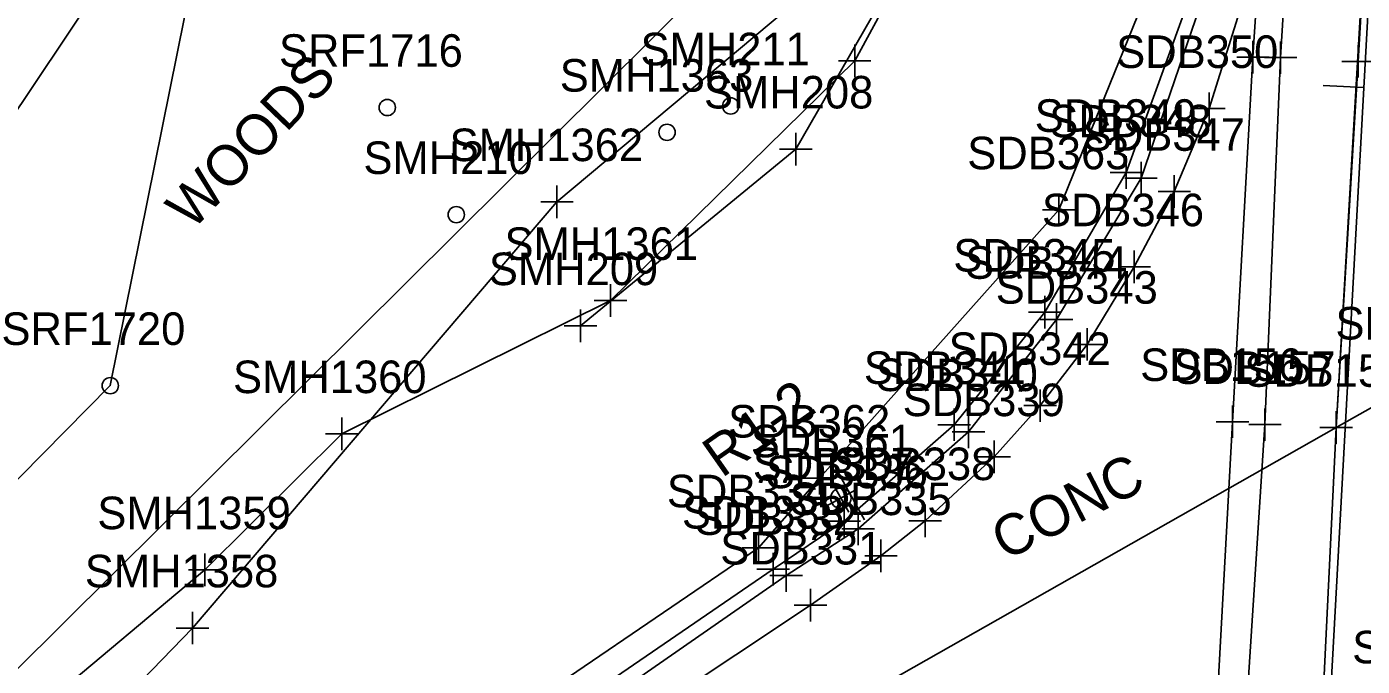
# Model space of a CAD drawing. Extents: x 941041 to 969446, y 397014 to 416764.
# Drawn here: x 951726.5 to 951890.6, y 403555.2 to 403633.8 of the extents above; entities that cross this region are included whole.
import ezdxf

# ---------------------------------------------------------------- set-up
doc = ezdxf.new("R2010")
doc.units = 0
for name, color, linetype in [('SURVEY - CENTERLINE - Preliminary', 7, 'Continuous'), ('SURVEY - CENTERLINE - Preliminary Curve Text', 7, 'Continuous'), ('SURVEY - DRAINAGE - Area Shapes', 7, 'Continuous'), ('SURVEY - DTM - Breaklines', 7, 'Continuous'), ('SURVEY - DTM - Breaklines - Points - Locators', 7, 'Continuous'), ('SURVEY - DTM - Breaklines - Points - Numbers', 7, 'Continuous'), ('SURVEY - DTM - Spot Points - Locators', 7, 'Continuous'), ('SURVEY - DTM - Spot Points - Point Numbers', 7, 'Continuous'), ('SURVEY - DTM GRAPHICS - Boundary Line', 7, 'Continuous'), ('SURVEY - NON-TRANSPORTATION - Features', 7, 'Continuous'), ('SURVEY - ROADSIDE BARRIERS - Points - Locators', 7, 'Continuous'), ('SURVEY - ROADSIDE BARRIERS - Points - Numbers', 7, 'Continuous'), ('SURVEY - ROADSIDE BARRIERS with Text', 7, 'Continuous'), ('SURVEY - TRAFFIC CONTROL - Signs - Points - Locators', 7, 'Continuous'), ('SURVEY - TRAFFIC CONTROL - Signs - Points - Numbers', 7, 'Continuous'), ('SURVEY - TRAFFIC CONTROL - Signs and Devices with Text', 7, 'Continuous'), ('SURVEY - TRANSPORTATION - Features Text', 7, 'Continuous'), ('SURVEY - TRANSPORTATION - Roads', 7, 'Continuous'), ('SURVEY - TRANSPORTATION - Roads - Points - Locators', 7, 'Continuous'), ('SURVEY - TRANSPORTATION - Roads - Points - Numbers', 7, 'Continuous'), ('SURVEY - VEGETATION - Features - Points - Locators', 7, 'Continuous'), ('SURVEY - VEGETATION - Features - Points - Numbers', 7, 'Continuous'), ('SURVEY - VEGETATION - Features with Text', 7, 'Continuous')]:
    doc.layers.add(name, color=color, linetype=linetype)

msp = doc.modelspace()

# ---------------------------------------------------------------- linework, layer by layer
at = {"layer": 'SURVEY - CENTERLINE - Preliminary'}
msp.add_line((951818.98, 402312.97), (951929.94, 404341.52), dxfattribs=at)
at = {"layer": 'SURVEY - CENTERLINE - Preliminary Curve Text'}
msp.add_line((951890.82, 403626.35), (951885.83, 403626.62), dxfattribs=at)
at = {"layer": 'SURVEY - DRAINAGE - Area Shapes'}
for points in [[(951394.91, 403299.54), (951490.14, 404032.2), (951534.57, 404027.31), (951536.74, 404050.34), (951913.12, 404038.39), (951897.46, 403756.49), (951887.41, 403584.59), (951722.84, 403491.25), (951657.46, 403432.19), (951570.1, 403333.86)], [(951145.6, 402792.15), (951562.19, 403084.02), (952475.83, 403724.71), (952754.77, 403922.8), (952578.99, 403846.21), (952455.44, 403792), (952334.19, 403750.29), (951972.51, 403632.53), (951887.41, 403584.59)]]:
    msp.add_lwpolyline(points, dxfattribs=at)
at = {"layer": 'SURVEY - DTM - Breaklines'}
for points in [[(951899.88, 403797.03), (951897.46, 403756.49), (951895.1, 403715.33), (951892.65, 403672.69), (951890.1, 403629.58), (951887.41, 403584.59), (951885.29, 403540.64), (951882.61, 403490.83), (951880.06, 403438.72), (951877.65, 403396.76)], [(951641.86, 403426.67), (951653.35, 403439.13), (951682.38, 403468.13), (951717.4, 403498.12), (951748.42, 403523.14), (951781.37, 403545.95), (951816.39, 403569.78), (951823.92, 403578.35), (951853.31, 403611.32), (951868.71, 403649.22), (951877.42, 403681.51), (951874.12, 403698.41), (951861.93, 403712.77), (951840.77, 403717.4), (951813.39, 403710.78), (951800.96, 403703.16), (951769.1, 403675.11), (951738.55, 403643.48)], [(951746.79, 403639.72), (951784.08, 403673.17), (951825.91, 403698.88), (951848.16, 403703.12), (951841.56, 403654.59), (951820.99, 403618.79), (951794.53, 403597.08)], [(951504.25, 403257.1), (951548.43, 403354.82), (951588.18, 403418.84), (951641.86, 403470.19), (951672.49, 403500.14), (951709.08, 403534.17), (951748.34, 403567.09), (951765.19, 403583.81), (951798.22, 403600.18), (951828.23, 403629.65), (951839.94, 403651.21), (951840.47, 403661.39)]]:
    msp.add_lwpolyline(points, dxfattribs=at)
at = {"layer": 'SURVEY - DTM - Breaklines - Points - Locators'}
for p, q in [((951828.23, 403631.65), (951828.23, 403627.65)), ((951890.1, 403631.58), (951890.1, 403627.58)), ((951830.23, 403629.65), (951826.23, 403629.65)), ((951892.1, 403629.58), (951888.1, 403629.58)), ((951820.99, 403620.79), (951820.99, 403616.79)), ((951822.99, 403618.79), (951818.99, 403618.79)), ((951853.31, 403613.32), (951853.31, 403609.32)), ((951855.31, 403611.32), (951851.31, 403611.32)), ((951798.22, 403602.18), (951798.22, 403598.18)), ((951794.53, 403599.08), (951794.53, 403595.08)), ((951800.22, 403600.18), (951796.22, 403600.18)), ((951796.53, 403597.08), (951792.53, 403597.08)), ((951765.19, 403585.81), (951765.19, 403581.81)), ((951887.41, 403586.59), (951887.41, 403582.59)), ((951889.41, 403584.59), (951885.41, 403584.59)), ((951767.19, 403583.81), (951763.19, 403583.81)), ((951823.92, 403580.35), (951823.92, 403576.35)), ((951825.92, 403578.35), (951821.92, 403578.35)), ((951816.39, 403571.78), (951816.39, 403567.78)), ((951818.39, 403569.78), (951814.39, 403569.78)), ((951748.34, 403569.09), (951748.34, 403565.09)), ((951750.34, 403567.09), (951746.34, 403567.09))]:
    msp.add_line(p, q, dxfattribs=at)
at = {"layer": 'SURVEY - DTM - Spot Points - Locators'}
for centre in [(951770.78, 403623.91), (951812.99, 403624.1), (951805.17, 403620.86), (951779.26, 403610.74), (951736.73, 403589.73)]:
    msp.add_circle(centre, 1, dxfattribs=at)
at = {"layer": 'SURVEY - DTM GRAPHICS - Boundary Line'}
msp.add_lwpolyline([(951575.07, 404018.69), (951594.81, 403959.15), (951592.33, 403907.04), (951593.34, 403830.61), (951643.02, 403826.18), (951710.4, 403762.77), (951727.47, 403714.2), (951716.98, 403687.98), (951730.3, 403662.6), (951739.47, 403650.39), (951738.55, 403643.5), (951746.79, 403639.72), (951736.73, 403589.73), (951706.43, 403559.07), (951672.49, 403500.14), (951641.86, 403470.19), (951622.56, 403452.94), (951588.18, 403418.84), (951548.43, 403354.82), (951490.75, 403254.61), (951405.32, 403106.55), (950864.72, 402727.75)], dxfattribs=at)
at = {"layer": 'SURVEY - NON-TRANSPORTATION - Features'}
msp.add_lwpolyline([(950864.72, 402727.75), (951405.32, 403106.55), (951490.75, 403254.61), (951622.56, 403452.94), (951851.46, 403680.18), (951878.49, 403682.56)], dxfattribs=at)
at = {"layer": 'SURVEY - ROADSIDE BARRIERS - Points - Locators'}
for p, q in [((951861.62, 403617.92), (951861.62, 403613.92)), ((951863.62, 403615.92), (951859.62, 403615.92)), ((951851.6, 403600.75), (951851.6, 403596.75)), ((951853.6, 403598.75), (951849.6, 403598.75)), ((951840.45, 403586.93), (951840.45, 403582.93)), ((951842.45, 403584.93), (951838.45, 403584.93)), ((951826.95, 403575.08), (951826.95, 403571.08)), ((951828.95, 403573.08), (951824.95, 403573.08)), ((951818.22, 403569.17), (951818.22, 403565.17)), ((951820.22, 403567.17), (951816.22, 403567.17))]:
    msp.add_line(p, q, dxfattribs=at)
at = {"layer": 'SURVEY - ROADSIDE BARRIERS with Text'}
msp.add_lwpolyline([(951653.32, 403436.82), (951685.14, 403466.86), (951718.82, 403496.01), (951750.67, 403520.29), (951783.21, 403543.21), (951818.22, 403567.17), (951826.95, 403573.08), (951840.45, 403584.93), (951851.6, 403598.75), (951861.62, 403615.92), (951871.85, 403644.2), (951877.9, 403666.33), (951881.14, 403687.36), (951881.18, 403694.17), (951880.19, 403699.57), (951876.73, 403707.33), (951867.26, 403722.8)], dxfattribs=at)
at = {"layer": 'SURVEY - TRAFFIC CONTROL - Signs - Points - Locators'}
for p, q in [((951827.51, 403574.17), (951825.56, 403577.67)), ((951824.79, 403574.94), (951828.29, 403576.89))]:
    msp.add_line(p, q, dxfattribs=at)
at = {"layer": 'SURVEY - TRAFFIC CONTROL - Signs and Devices with Text'}
msp.add_line((951825.78, 403579.79), (951829.44, 403573.24), dxfattribs=at)
msp.add_circle((951826.53, 403575.89), 1.25, dxfattribs=at)
at = {"layer": 'SURVEY - TRANSPORTATION - Roads'}
for points in [[(951889.67, 403798.15), (951887.47, 403762.39), (951886.39, 403756.98), (951884.11, 403714.99), (951881.77, 403672.24), (951879.03, 403658.08), (951877.19, 403630.1), (951874.68, 403585.3), (951872.31, 403541.8), (951869.92, 403493.49), (951868.53, 403439.12), (951866.21, 403388.53), (951867.61, 403389.53)], [(951889.67, 403798.15), (951887.47, 403762.39), (951886.39, 403756.98), (951884.11, 403714.99), (951881.77, 403672.24), (951879.03, 403658.08), (951877.19, 403630.1), (951874.68, 403585.3), (951872.31, 403541.8), (951869.92, 403493.49), (951868.53, 403439.12), (951866.69, 403400.46)], [(951890.4, 403798.17), (951888, 403756.83), (951885.32, 403715.18), (951883.22, 403673.16), (951880.59, 403630.04), (951878.66, 403584.94), (951875.81, 403541.16), (951872.77, 403491.83), (951870.34, 403439.11), (951867.61, 403389.53)], [(951411.81, 403052.83), (951433.79, 403086.48), (951455, 403125.01), (951474.14, 403165.06), (951492.87, 403205.4), (951511.64, 403243.43), (951531.76, 403279.81), (951554.15, 403314.52), (951581.05, 403351.18), (951610.77, 403387.99), (951640.83, 403422.39), (951654.46, 403436.04), (951686.11, 403466.26), (951719.67, 403495.18), (951751.88, 403518.68), (951783.82, 403541.39), (951819.82, 403566.39), (951828.66, 403572.13), (951842.23, 403584.06), (951853.04, 403597.86), (951863.43, 403615.24), (951873.23, 403643.85), (951879.03, 403658.08)], [(951536.17, 403276.66), (951558.52, 403311.6), (951584.36, 403348.13), (951613.6, 403384.66), (951644.16, 403418.6), (951657.46, 403432.19), (951689.75, 403463.06), (951722.84, 403491.25), (951754.66, 403515.84), (951785.97, 403538.25), (951822.79, 403562.75), (951831.46, 403568.82), (951836.89, 403573.12), (951845.38, 403580.98), (951851.02, 403587.27), (951856.81, 403594.8), (951862.6, 403604.32), (951867.52, 403613.59), (951871.79, 403623.77), (951877.94, 403643.39)]]:
    msp.add_lwpolyline(points, dxfattribs=at)
at = {"layer": 'SURVEY - TRANSPORTATION - Roads - Points - Locators'}
for p, q in [((951877.19, 403632.1), (951877.19, 403628.1)), ((951880.59, 403632.04), (951880.59, 403628.04)), ((951879.19, 403630.1), (951875.19, 403630.1)), ((951882.59, 403630.04), (951878.59, 403630.04)), ((951871.79, 403625.77), (951871.79, 403621.77)), ((951873.79, 403623.77), (951869.79, 403623.77)), ((951863.43, 403617.24), (951863.43, 403613.24)), ((951867.52, 403615.59), (951867.52, 403611.59)), ((951865.43, 403615.24), (951861.43, 403615.24)), ((951869.52, 403613.59), (951865.52, 403613.59)), ((951862.6, 403606.32), (951862.6, 403602.32)), ((951864.6, 403604.32), (951860.6, 403604.32)), ((951853.04, 403599.86), (951853.04, 403595.86)), ((951855.04, 403597.86), (951851.04, 403597.86)), ((951856.81, 403596.8), (951856.81, 403592.8)), ((951858.81, 403594.8), (951854.81, 403594.8)), ((951851.02, 403589.27), (951851.02, 403585.27)), ((951842.23, 403586.06), (951842.23, 403582.06)), ((951853.02, 403587.27), (951849.02, 403587.27)), ((951874.68, 403587.3), (951874.68, 403583.3)), ((951878.66, 403586.94), (951878.66, 403582.94)), ((951876.68, 403585.3), (951872.68, 403585.3)), ((951880.66, 403584.94), (951876.66, 403584.94)), ((951844.23, 403584.06), (951840.23, 403584.06)), ((951845.38, 403582.98), (951845.38, 403578.98)), ((951847.38, 403580.98), (951843.38, 403580.98)), ((951836.89, 403575.12), (951836.89, 403571.12)), ((951828.66, 403574.13), (951828.66, 403570.13)), ((951838.89, 403573.12), (951834.89, 403573.12)), ((951830.66, 403572.13), (951826.66, 403572.13)), ((951831.46, 403570.82), (951831.46, 403566.82)), ((951819.82, 403568.39), (951819.82, 403564.39)), ((951833.46, 403568.82), (951829.46, 403568.82)), ((951821.82, 403566.39), (951817.82, 403566.39)), ((951822.79, 403564.75), (951822.79, 403560.75)), ((951824.79, 403562.75), (951820.79, 403562.75))]:
    msp.add_line(p, q, dxfattribs=at)
at = {"layer": 'SURVEY - VEGETATION - Features - Points - Locators'}
for p, q in [((951791.64, 403614.32), (951791.64, 403610.32)), ((951793.64, 403612.32), (951789.64, 403612.32)), ((951746.84, 403561.94), (951746.84, 403557.94)), ((951748.84, 403559.94), (951744.84, 403559.94))]:
    msp.add_line(p, q, dxfattribs=at)
at = {"layer": 'SURVEY - VEGETATION - Features with Text'}
msp.add_lwpolyline([(951868.69, 403693.52), (951860.48, 403665.55), (951848.34, 403659.79), (951791.64, 403612.32), (951746.84, 403559.94), (951643.65, 403453.43), (951600.78, 403415.7), (951529.23, 403307.04), (951432.31, 403122.21), (951397.48, 403082.19), (951387.06, 403063.16), (951343.99, 403026.97), (951317.91, 403024.99), (951275.96, 402980.18), (951202.21, 402921.55), (951122.62, 402900.03), (951100.62, 402857.44), (951081.13, 402854.56), (950864.72, 402727.75), (951405.32, 403106.55), (951588.18, 403418.84), (951738.55, 403643.48), (951840.77, 403717.4), (951868.69, 403693.52)], dxfattribs=at)

# ---------------------------------------------------------------- texts
at = {"layer": 'SURVEY - DTM - Breaklines - Points - Numbers'}
for s, p in [('SMH208', (951809.71, 403623.79)), ('SDB363', (951842.07, 403616.32)), ('SMH1361', (951785.19, 403605.18)), ('SMH209', (951783.27, 403602.08)), ('SMH1360', (951751.82, 403588.81)), ('SDB158', (951876.12, 403589.59)), ('SDB362', (951812.68, 403583.35)), ('SDB334', (951805.15, 403574.78)), ('SMH1359', (951735.14, 403572.09))]:
    msp.add_text(s, height=4, dxfattribs=at).set_placement(p)
at = {"layer": 'SURVEY - DTM - Spot Points - Point Numbers'}
for s, p in [('SRF1716', (951757.47, 403628.91)), ('SMH211', (951801.91, 403629.1)), ('SMH1363', (951791.98, 403625.86)), ('SMH210', (951767.85, 403615.74)), ('SRF1720', (951723.36, 403594.73))]:
    msp.add_text(s, height=4, dxfattribs=at).set_placement(p)
at = {"layer": 'SURVEY - ROADSIDE BARRIERS - Points - Numbers'}
for s, p in [('SDB349', (951850.36, 403620.92)), ('SDB345', (951840.36, 403603.75)), ('SDB341', (951829.36, 403589.93)), ('SDB337', (951815.71, 403578.08)), ('SDB333', (951806.99, 403572.17))]:
    msp.add_text(s, height=4, dxfattribs=at).set_placement(p)
at = {"layer": 'SURVEY - TRAFFIC CONTROL - Signs - Points - Numbers'}
msp.add_text('SDB361', height=4, dxfattribs=at).set_placement((951815.46, 403580.92))
at = {"layer": 'SURVEY - TRAFFIC CONTROL - Signs and Devices with Text'}
msp.add_text('R1-2', height=5, rotation=35, dxfattribs=at).set_placement((951811.89, 403578.31))
at = {"layer": 'SURVEY - TRANSPORTATION - Features Text'}
msp.add_text('CONC', height=5, rotation=27.167, dxfattribs=at).set_placement((951846.75, 403568.16))
at = {"layer": 'SURVEY - TRANSPORTATION - Roads - Points - Numbers'}
for s, p in [('SDB350', (951860.38, 403628.77)), ('SDB348', (951852.15, 403620.24)), ('SDB347', (951856.28, 403618.59)), ('SDB346', (951851.25, 403609.32)), ('SDB344', (951841.8, 403602.86)), ('SDB343', (951845.57, 403599.8)), ('SMH128', (951887.33, 403595.4)), ('SDB342', (951839.78, 403592.27)), ('SDB156', (951863.33, 403590.3)), ('SDB157', (951867.42, 403589.94)), ('SDB340', (951830.82, 403589.06)), ('SDB339', (951834.13, 403585.98)), ('SDB336', (951817.31, 403577.13)), ('SDB338', (951825.6, 403578.12)), ('SDB335', (951820.23, 403573.82)), ('SDB332', (951808.58, 403571.39)), ('SDB331', (951811.71, 403567.75)), ('SSH228', (951889.39, 403555.6))]:
    msp.add_text(s, height=4, dxfattribs=at).set_placement(p)
at = {"layer": 'SURVEY - VEGETATION - Features - Points - Numbers'}
for s, p in [('SMH1362', (951778.44, 403617.32)), ('SMH1358', (951733.6, 403564.94))]:
    msp.add_text(s, height=4, dxfattribs=at).set_placement(p)
at = {"layer": 'SURVEY - VEGETATION - Features with Text'}
msp.add_text('WOODS', height=4.998, rotation=46.273, dxfattribs=at).set_placement((951746.8, 403608.68))

doc.saveas('drawing.dxf')
